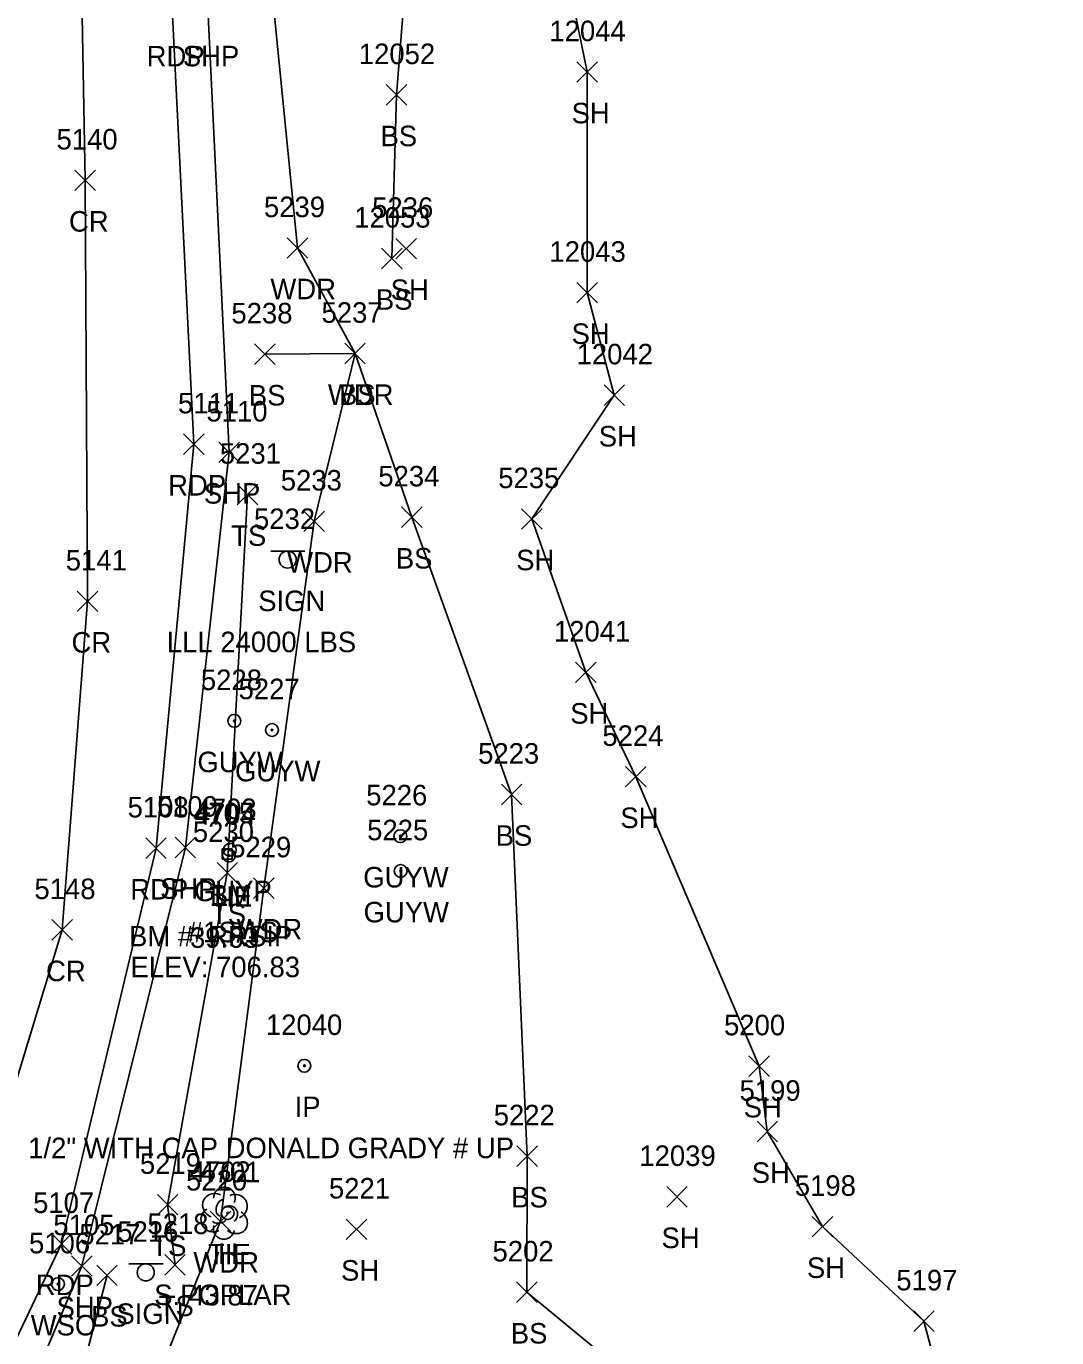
# Model space of a CAD drawing. Extents: x 1769141 to 1770911, y 735471 to 741449.
# Drawn here: x 1770761.1 to 1770861.5, y 739354.5 to 739482.3 of the extents above; entities that cross this region are included whole.
import ezdxf

# ---------------------------------------------------------------- set-up
doc = ezdxf.new("R2010")
doc.units = 0
for name, color, linetype in [('C_A', 7, 'Continuous'), ('C_C', 7, 'Continuous'), ('C_I', 7, 'Continuous'), ('CBP', 7, 'Continuous'), ('CPBM', 7, 'Continuous'), ('L_A', 7, 'Continuous'), ('L_C', 7, 'Continuous'), ('L_I', 7, 'Continuous'), ('L_TIC', 7, 'Continuous'), ('LAWA', 7, 'Continuous'), ('LELB', 7, 'Continuous'), ('LSOGP', 7, 'Continuous'), ('LTD', 7, 'Continuous'), ('M_A', 7, 'Continuous'), ('M_C', 7, 'Continuous'), ('M_I', 7, 'Continuous'), ('MPIR', 7, 'Continuous'), ('P_A', 7, 'Continuous'), ('P_I', 7, 'Continuous'), ('P_TIC', 7, 'Continuous'), ('PET', 7, 'Continuous'), ('PRC', 7, 'Continuous'), ('PSP', 7, 'Continuous'), ('S_A', 7, 'Continuous'), ('S_C', 7, 'Continuous'), ('S_I', 7, 'Continuous'), ('SSGN', 7, 'Continuous'), ('U_A', 7, 'Continuous'), ('U_C', 7, 'Continuous'), ('U_I', 7, 'Continuous'), ('UPGW', 7, 'Continuous'), ('UWV', 7, 'Continuous')]:
    doc.layers.add(name, color=color, linetype=linetype)

msp = doc.modelspace()

# ---------------------------------------------------------------- linework, layer by layer
at = {"layer": 'CBP'}
for centre, radius in [((1770780.88, 739401.53), 0.625), ((1770780.88, 739401.53), 0.0833), ((1770780.75, 739366.69), 0.625), ((1770780.75, 739366.69), 0.0833)]:
    msp.add_circle(centre, radius, dxfattribs=at)
at = {"layer": 'CPBM'}
for p, q in [((1770780.2, 739401.17), (1770780.2, 739402.17)), ((1770780.2, 739402.17), (1770781.2, 739402.17)), ((1770781.2, 739402.17), (1770781.2, 739401.17)), ((1770781.2, 739401.17), (1770780.2, 739401.17)), ((1770780.7, 739401.67), (1770780.7, 739401.67)), ((1770780.7, 739401.67), (1770780.7, 739401.67))]:
    msp.add_line(p, q, dxfattribs=at)
at = {"layer": 'L_TIC'}
for points in [[(1770814.75, 739476.85), (1770816.75, 739478.85)], [(1770816.75, 739476.85), (1770814.75, 739478.85)], [(1770796.19, 739474.62), (1770798.19, 739476.62)], [(1770798.19, 739474.62), (1770796.19, 739476.62)], [(1770786.55, 739459.71), (1770788.55, 739461.71)], [(1770788.55, 739459.71), (1770786.55, 739461.71)], [(1770795.74, 739458.69), (1770797.74, 739460.69)], [(1770797.74, 739458.69), (1770795.74, 739460.69)], [(1770797.13, 739459.64), (1770799.13, 739461.64)], [(1770799.13, 739459.64), (1770797.13, 739461.64)], [(1770814.75, 739455.36), (1770816.75, 739457.36)], [(1770816.75, 739455.36), (1770814.75, 739457.36)], [(1770783.37, 739449.36), (1770785.37, 739451.36)], [(1770785.37, 739449.36), (1770783.37, 739451.36)], [(1770792.15, 739449.42), (1770794.15, 739451.42)], [(1770794.15, 739449.42), (1770792.15, 739451.42)], [(1770792.15, 739449.42), (1770794.15, 739451.42)], [(1770794.15, 739449.42), (1770792.15, 739451.42)], [(1770817.4, 739445.37), (1770819.4, 739447.37)], [(1770819.4, 739445.37), (1770817.4, 739447.37)], [(1770781.68, 739435.69), (1770783.68, 739437.69)], [(1770783.68, 739435.69), (1770781.68, 739437.69)], [(1770788.18, 739433.08), (1770790.18, 739435.08)], [(1770790.18, 739433.08), (1770788.18, 739435.08)], [(1770797.68, 739433.48), (1770799.68, 739435.48)], [(1770799.68, 739433.48), (1770797.68, 739435.48)], [(1770809.36, 739433.31), (1770811.36, 739435.31)], [(1770811.36, 739433.31), (1770809.36, 739435.31)], [(1770814.62, 739418.37), (1770816.62, 739420.37)], [(1770816.62, 739418.37), (1770814.62, 739420.37)], [(1770819.5, 739408.2), (1770821.5, 739410.2)], [(1770821.5, 739408.2), (1770819.5, 739410.2)], [(1770807.4, 739406.47), (1770809.4, 739408.47)], [(1770809.4, 739406.47), (1770807.4, 739408.47)], [(1770779.71, 739398.84), (1770781.71, 739400.84)], [(1770781.71, 739398.84), (1770779.71, 739400.84)], [(1770783.26, 739397.35), (1770785.26, 739399.35)], [(1770785.26, 739397.35), (1770783.26, 739399.35)], [(1770831.51, 739380.01), (1770833.51, 739382.01)], [(1770833.51, 739380.01), (1770831.51, 739382.01)], [(1770832.3, 739373.63), (1770834.3, 739375.63)], [(1770834.3, 739373.63), (1770832.3, 739375.63)], [(1770808.92, 739371.24), (1770810.92, 739373.24)], [(1770810.92, 739371.24), (1770808.92, 739373.24)], [(1770823.51, 739367.28), (1770825.51, 739369.28)], [(1770825.51, 739367.28), (1770823.51, 739369.28)], [(1770773.9, 739366.51), (1770775.9, 739368.51)], [(1770775.9, 739366.51), (1770773.9, 739368.51)], [(1770779.05, 739364.89), (1770781.05, 739366.89)], [(1770781.05, 739364.89), (1770779.05, 739366.89)], [(1770792.3, 739364.11), (1770794.3, 739366.11)], [(1770794.3, 739364.11), (1770792.3, 739366.11)], [(1770837.67, 739364.37), (1770839.67, 739366.37)], [(1770839.67, 739364.37), (1770837.67, 739366.37)], [(1770774.62, 739360.65), (1770776.62, 739362.65)], [(1770776.62, 739360.65), (1770774.62, 739362.65)], [(1770768, 739359.63), (1770770, 739361.63)], [(1770770, 739359.63), (1770768, 739361.63)], [(1770808.88, 739357.98), (1770810.88, 739359.98)], [(1770810.88, 739357.98), (1770808.88, 739359.98)], [(1770847.56, 739355.16), (1770849.56, 739357.16)], [(1770849.56, 739355.16), (1770847.56, 739357.16)]]:
    msp.add_lwpolyline(points, dxfattribs=at)
at = {"layer": 'LAWA'}
msp.add_lwpolyline([(1770848.36, 739299.29), (1770819.39, 739316.36), (1770796.34, 739325.69), (1770784.74, 739317.06), (1770772.09, 739329.99), (1770772.76, 739337.11), (1770771.58, 739344.84), (1770780.05, 739365.89), (1770784.26, 739398.35), (1770789.18, 739434.08), (1770793.15, 739450.42), (1770787.55, 739460.71), (1770784.38, 739492.83), (1770781.25, 739542.67), (1770782.94, 739547.81), (1770785.04, 739555.61), (1770781.08, 739568.95)], dxfattribs=at)
at = {"layer": 'LELB'}
for points in [[(1770784.96, 739569.82), (1770787.4, 739522.92), (1770799, 739498.49), (1770797.19, 739475.62), (1770796.74, 739459.69)], [(1770853.39, 739338.06), (1770842.11, 739339.46), (1770825.99, 739345.71), (1770809.88, 739358.98), (1770809.92, 739372.24), (1770808.4, 739407.47), (1770798.68, 739434.48), (1770793.15, 739450.42), (1770784.37, 739450.36)], [(1770775.62, 739361.65), (1770774.9, 739367.51), (1770780.71, 739399.84), (1770782.68, 739436.69)], [(1770765.92, 739330.63), (1770769.02, 739335.36), (1770770.15, 739338), (1770765.2, 739346.07), (1770769, 739360.63)]]:
    msp.add_lwpolyline(points, dxfattribs=at)
at = {"layer": 'LSOGP'}
msp.add_lwpolyline([(1770861.49, 739273.14), (1770848.36, 739299.29), (1770853.39, 739338.06), (1770848.56, 739356.16), (1770838.67, 739365.37), (1770833.3, 739374.63), (1770832.51, 739381.01), (1770820.5, 739409.2), (1770815.62, 739419.37), (1770810.36, 739434.31), (1770818.4, 739446.37), (1770815.75, 739456.36), (1770815.75, 739477.85), (1770810.87, 739501.85)], dxfattribs=at)
at = {"layer": 'LTD'}
msp.add_line((1770780.39, 739366.73), (1770780.39, 739366.73), dxfattribs=at)
msp.add_line((1770780.39, 739366.73), (1770780.39, 739366.73), dxfattribs=at)
msp.add_arc((1770780.43, 739368.17), 1.05, 335.5272, 180.9563, dxfattribs=at)
for centre, major_axis, ratio, start_param, end_param in [((1770779.6, 739367.4), (1.21, -0.51), 0.895232, 1.570796, 4.712389), ((1770781.43, 739367.32), (-1.14, -0.48), 0.949671, 1.570796, 4.712389), ((1770780.18, 739367.19), (-0.208, -0.792), 0.645439, 3.141593, 6.283185), ((1770780.89, 739366.57), (-0.5, 0.667), 0.989748, 3.141593, 6.283185), ((1770779.3, 739366.03), (0.58, -1.04), 0.959034, 3.141593, 6.283185), ((1770779.93, 739365.98), (-0.625, -0.083), 0.423636, 0, 3.141593), ((1770781.39, 739365.9), (-1.09, 0.79), 0.841452, 1.570796, 4.712389), ((1770780.39, 739365.23), (0.26, 1.06), 0.942809, 1.570796, 4.712389)]:
    msp.add_ellipse(centre, major_axis=major_axis, ratio=ratio, start_param=start_param, end_param=end_param, dxfattribs=at)
at = {"layer": 'MPIR'}
for radius in [0.625, 0.0833]:
    msp.add_circle((1770788.22, 739381.04), radius, dxfattribs=at)
at = {"layer": 'P_TIC'}
for points in [[(1770765.86, 739466.3), (1770767.86, 739468.3)], [(1770767.86, 739466.3), (1770765.86, 739468.3)], [(1770776.46, 739440.59), (1770778.46, 739442.59)], [(1770778.46, 739440.59), (1770776.46, 739442.59)], [(1770779.9, 739439.8), (1770781.9, 739441.8)], [(1770781.9, 739439.8), (1770779.9, 739441.8)], [(1770766.1, 739425.29), (1770768.1, 739427.29)], [(1770768.1, 739425.29), (1770766.1, 739427.29)], [(1770772.77, 739401.23), (1770774.77, 739403.23)], [(1770774.77, 739401.23), (1770772.77, 739403.23)], [(1770775.63, 739401.31), (1770777.63, 739403.31)], [(1770777.63, 739401.31), (1770775.63, 739403.31)], [(1770763.63, 739393.28), (1770765.63, 739395.28)], [(1770765.63, 739393.28), (1770763.63, 739395.28)], [(1770763.58, 739362.7), (1770765.58, 739364.7)], [(1770765.58, 739362.7), (1770763.58, 739364.7)], [(1770765.54, 739360.54), (1770767.54, 739362.54)], [(1770767.54, 739360.54), (1770765.54, 739362.54)]]:
    msp.add_lwpolyline(points, dxfattribs=at)
at = {"layer": 'PET'}
msp.add_lwpolyline([(1770826.12, 739215.62), (1770808.71, 739238.73), (1770793.69, 739255.36), (1770777.1, 739279.15), (1770747.52, 739317.6), (1770746.21, 739323.83), (1770749.6, 739332.28), (1770764.58, 739363.7), (1770773.77, 739402.23), (1770777.46, 739441.59), (1770775.37, 739483.39), (1770773.97, 739524.69), (1770772.74, 739572.79)], dxfattribs=at)
at = {"layer": 'PRC'}
msp.add_lwpolyline([(1770765.46, 739577.52), (1770766.25, 739541.4), (1770766.22, 739502.8), (1770766.86, 739467.3), (1770767.1, 739426.29), (1770764.63, 739394.28), (1770755.81, 739365.32), (1770741.41, 739349.32), (1770728.38, 739342.71)], dxfattribs=at)
at = {"layer": 'PSP'}
msp.add_lwpolyline([(1770777.1, 739279.15), (1770772.36, 739289.78), (1770763.28, 739301.07), (1770753.08, 739312.06), (1770750.64, 739316.97), (1770751.24, 739320.46), (1770749.65, 739321.47), (1770748.44, 739321.99), (1770752.14, 739330.24), (1770753.96, 739331.67), (1770766.54, 739361.54), (1770776.63, 739402.31), (1770780.9, 739440.8), (1770778.84, 739483.4), (1770777.57, 739524.87), (1770775.93, 739572.48), (1770777.8, 739574.14), (1770778.96, 739574.79), (1770778.9, 739578.76)], dxfattribs=at)
at = {"layer": 'SSGN'}
for p, q in [((1770784.94, 739431.18), (1770788.27, 739431.18)), ((1770786.59, 739430.35), (1770786.59, 739430.35)), ((1770771.12, 739361.74), (1770774.46, 739361.74)), ((1770772.77, 739360.91), (1770772.77, 739360.91))]:
    msp.add_line(p, q, dxfattribs=at)
for centre in [(1770786.59, 739430.35), (1770772.77, 739360.91)]:
    msp.add_circle(centre, 0.833, dxfattribs=at)
at = {"layer": 'UPGW'}
for centre, radius in [((1770781.4, 739414.64), 0.625), ((1770781.4, 739414.64), 0.0833), ((1770785.07, 739413.75), 0.625), ((1770785.07, 739413.75), 0.0833), ((1770797.56, 739403.41), 0.625), ((1770797.56, 739403.41), 0.0833), ((1770780.96, 739402.07), 0.625), ((1770780.96, 739402.07), 0.0833), ((1770797.59, 739400.01), 0.625), ((1770797.59, 739400.01), 0.0833)]:
    msp.add_circle(centre, radius, dxfattribs=at)
at = {"layer": 'UWV'}
for radius in [0.625, 0.0833]:
    msp.add_circle((1770764.23, 739359.77), radius, dxfattribs=at)

# ---------------------------------------------------------------- texts
at = {"layer": 'C_A'}
for s, p in [('TIE', (1770778.96, 739396.53)), ('BM', (1770779.02, 739396.67)), ('TIE', (1770778.83, 739361.69))]:
    msp.add_text(s, height=2, dxfattribs=at).set_placement(p)
at = {"layer": 'C_C'}
for s, p in [('BM #  RRSIP', (1770771.14, 739392.67)), ('39.63', (1770777.08, 739392.53)), ('ELEV: 706.83', (1770771.29, 739389.67)), ('43.87', (1770777, 739357.69))]:
    msp.add_text(s, height=2, dxfattribs=at).set_placement(p)
at = {"layer": 'C_I'}
for s, p in [('4705', (1770777.37, 739404.67)), ('4704', (1770777.54, 739404.53)), ('4701', (1770777.98, 739369.69))]:
    msp.add_text(s, height=2, dxfattribs=at).set_placement(p)
at = {"layer": 'L_A'}
for s, p in [('SH', (1770814.24, 739472.85)), ('BS', (1770795.63, 739470.62)), ('WDR', (1770784.91, 739455.71)), ('BS', (1770795.18, 739454.69)), ('SH', (1770796.62, 739455.64)), ('SH', (1770814.24, 739451.36)), ('BS', (1770782.81, 739445.36)), ('WDR', (1770790.51, 739445.42)), ('BS', (1770791.59, 739445.42)), ('SH', (1770816.89, 739441.37)), ('TS', (1770781.09, 739431.69)), ('BS', (1770797.12, 739429.48)), ('SH', (1770808.85, 739429.31)), ('WDR', (1770786.54, 739429.08)), ('SH', (1770814.11, 739414.37)), ('SH', (1770818.99, 739404.2)), ('BS', (1770806.84, 739402.47)), ('TS', (1770779.12, 739394.84)), ('WDR', (1770781.62, 739393.35)), ('SH', (1770831, 739376.01)), ('SH', (1770831.79, 739369.63)), ('BS', (1770808.36, 739367.24)), ('SH', (1770823, 739363.28)), ('TS', (1770773.31, 739362.51)), ('H', (1770779.82, 739361.73)), ('WDR', (1770777.41, 739360.89)), ('SH', (1770837.16, 739360.37)), ('SH', (1770791.79, 739360.11)), ('TS', (1770774.03, 739356.65)), ('BS', (1770767.44, 739355.63)), ('BS', (1770808.32, 739353.98))]:
    msp.add_text(s, height=2, dxfattribs=at).set_placement(p)
at = {"layer": 'L_C'}
msp.add_text('S.POPLAR', height=2, dxfattribs=at).set_placement((1770773.59, 739357.73))
at = {"layer": 'L_I'}
for s, p in [('12044', (1770812.08, 739480.85)), ('12052', (1770793.52, 739478.62)), ('5239', (1770784.28, 739463.71)), ('5236', (1770794.82, 739463.64)), ('12053', (1770793.07, 739462.69)), ('12043', (1770812.08, 739459.36)), ('5237', (1770789.89, 739453.42)), ('5237', (1770789.89, 739453.42)), ('5238', (1770781.11, 739453.36)), ('12042', (1770814.73, 739449.37)), ('5231', (1770779.99, 739439.69)), ('5233', (1770785.92, 739437.08)), ('5234', (1770795.42, 739437.48)), ('5235', (1770807.1, 739437.31)), ('12041', (1770812.52, 739422.37)), ('5224', (1770817.24, 739412.2)), ('5223', (1770805.14, 739410.47)), ('5230', (1770777.36, 739402.84)), ('5229', (1770780.99, 739401.35)), ('5200', (1770829.09, 739384.01)), ('5199', (1770830.6, 739377.63)), ('5222', (1770806.66, 739375.24)), ('5219', (1770772.2, 739370.51)), ('12039', (1770820.84, 739371.28)), ('4702', (1770777.05, 739369.73)), ('5220', (1770776.7, 739368.89)), ('5221', (1770790.61, 739368.11)), ('5198', (1770835.98, 739368.37)), ('5218', (1770772.93, 739364.65)), ('5217', (1770766.3, 739363.63)), ('5202', (1770806.54, 739361.98)), ('5197', (1770845.87, 739359.16))]:
    msp.add_text(s, height=2, dxfattribs=at).set_placement(p)
at = {"layer": 'M_A'}
msp.add_text('IP', height=2, dxfattribs=at).set_placement((1770787.27, 739376.04))
at = {"layer": 'M_C'}
msp.add_text('1/2" WITH CAP DONALD GRADY # UP', height=2, dxfattribs=at).set_placement((1770761.32, 739372.04))
at = {"layer": 'M_I'}
msp.add_text('12040', height=2, dxfattribs=at).set_placement((1770784.47, 739384.04))
at = {"layer": 'P_A'}
for s, p in [('RDP', (1770772.86, 739478.39)), ('SHP', (1770776.38, 739478.4)), ('CR', (1770765.29, 739462.3)), ('RDP', (1770774.95, 739436.59)), ('SHP', (1770778.43, 739435.8)), ('CR', (1770765.54, 739421.29)), ('RDP', (1770771.26, 739397.23)), ('SHP', (1770774.16, 739397.31)), ('CR', (1770763.06, 739389.28)), ('RDP', (1770762.06, 739358.7)), ('SHP', (1770764.08, 739356.54))]:
    msp.add_text(s, height=2, dxfattribs=at).set_placement(p)
at = {"layer": 'P_I'}
for s, p in [('5140', (1770764.08, 739470.3)), ('5111', (1770775.91, 739444.59)), ('5110', (1770778.68, 739443.8)), ('5141', (1770764.98, 739429.29)), ('5108', (1770771, 739405.23)), ('5109', (1770773.85, 739405.31)), ('5148', (1770761.93, 739397.28)), ('5107', (1770761.8, 739366.7)), ('5105', (1770763.77, 739364.54))]:
    msp.add_text(s, height=2, dxfattribs=at).set_placement(p)
at = {"layer": 'S_A'}
for p in [(1770783.72, 739425.33), (1770769.91, 739355.89)]:
    msp.add_text('SIGN', height=2, dxfattribs=at).set_placement(p)
at = {"layer": 'S_C'}
msp.add_text('LLL 24000 LBS', height=2, dxfattribs=at).set_placement((1770774.82, 739421.33))
at = {"layer": 'S_I'}
for s, p in [('5232', (1770783.31, 739433.33)), ('5216', (1770770, 739363.89))]:
    msp.add_text(s, height=2, dxfattribs=at).set_placement(p)
at = {"layer": 'U_A'}
for s, p in [('GUYW', (1770777.8, 739409.64)), ('GUYW', (1770781.46, 739408.75)), ('GUYW', (1770793.95, 739398.41)), ('GUYP', (1770777.47, 739397.07)), ('GUYW', (1770793.98, 739395.01)), ('WSO', (1770761.56, 739354.77))]:
    msp.add_text(s, height=2, dxfattribs=at).set_placement(p)
at = {"layer": 'U_C'}
msp.add_text('#1S/1S', height=2, dxfattribs=at).set_placement((1770776.86, 739393.07))
at = {"layer": 'U_I'}
for s, p in [('5228', (1770778.14, 739417.64)), ('5227', (1770781.81, 739416.75)), ('5226', (1770794.24, 739406.41)), ('4703', (1770777.62, 739405.07)), ('5225', (1770794.33, 739403.01)), ('5106', (1770761.4, 739362.77))]:
    msp.add_text(s, height=2, dxfattribs=at).set_placement(p)

doc.saveas('drawing.dxf')
